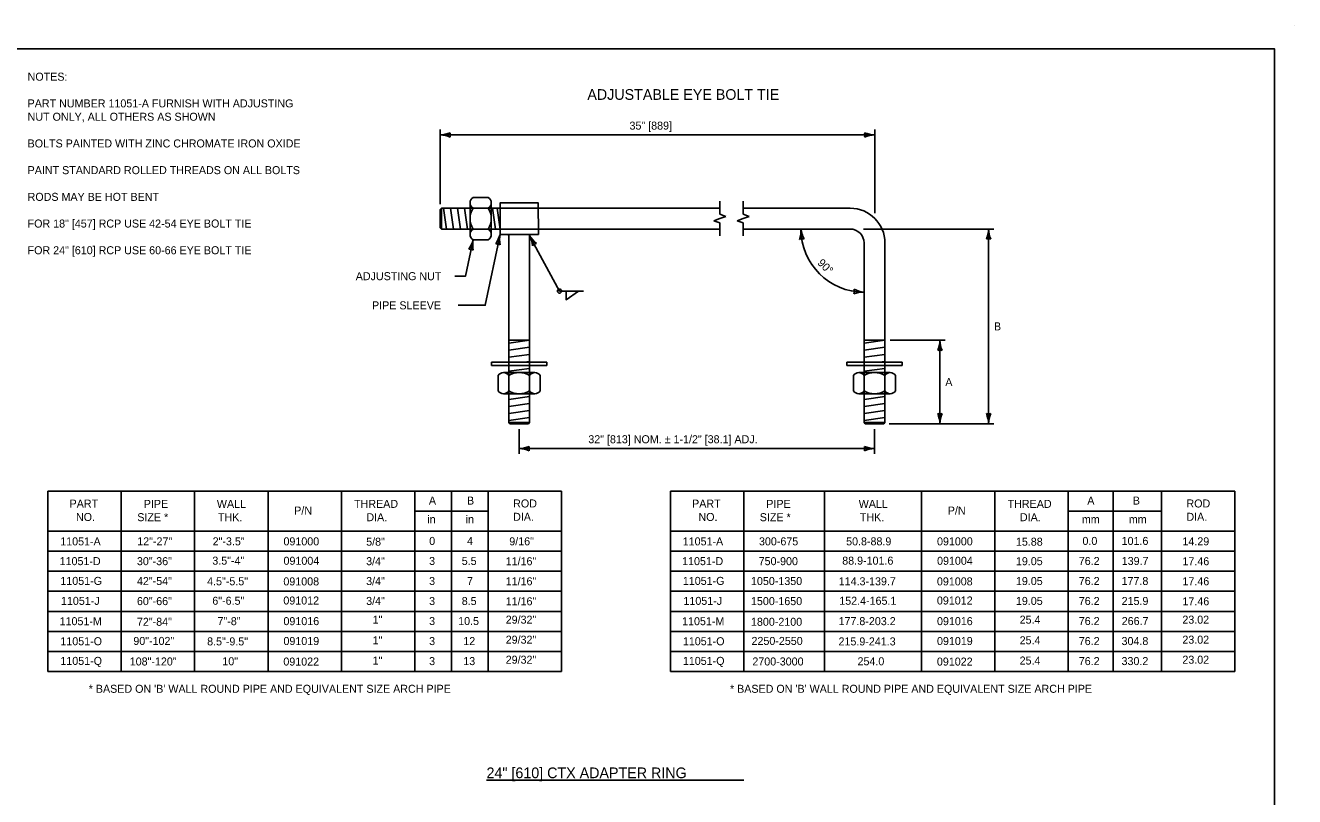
# Model space of a CAD drawing. Extents: x 49991.4 to 50021, y 49987.6 to 50011.4.
# Drawn here: x 50007.38 to 50016.9, y 49993.4 to 49999.18 of the extents above; entities that cross this region are included whole.
import ezdxf

# ---------------------------------------------------------------- set-up
doc = ezdxf.new("R2010")
doc.units = 0
for name, color, linetype in [('Level 1', 7, 'Continuous'), ('Level 2', 7, 'Continuous'), ('Level 3', 7, 'Continuous'), ('Level 4', 7, 'Continuous'), ('Level 6', 7, 'Continuous')]:
    doc.layers.add(name, color=color, linetype=linetype)

# ---------------------------------------------------------------- blocks, each defined once
blk = doc.blocks.new('HCUT')
at = {"layer": 'Level 6'}
for p, q in [((-0.0324, 0.0914), (-0.0648, 0)), ((-0.0324, 0.0914), (0, 0)), ((0, 0), (0.0324, -0.0914)), ((0.0648, 0), (0.0324, -0.0914))]:
    blk.add_line(p, q, dxfattribs=at)

msp = doc.modelspace()

# ---------------------------------------------------------------- linework, layer by layer
at = {"layer": 'Level 1'}
for p, q in [((50016.9001, 49999.1756), (50016.9001, 49999.1756)), ((50010.855, 49997.8864), (50010.7412, 49997.8864)), ((50010.4943, 49997.7976), (50010.5033, 49997.8066)), ((50010.4943, 49997.6593), (50010.4943, 49997.7976)), ((50010.5033, 49997.8066), (50010.9431, 49997.8066)), ((50010.5033, 49997.6504), (50010.5033, 49997.8066)), ((50010.5408, 49997.6504), (50010.5189, 49997.8066)), ((50010.5934, 49997.6504), (50010.5715, 49997.8066)), ((50010.646, 49997.6504), (50010.6241, 49997.8066)), ((50010.6986, 49997.6504), (50010.6766, 49997.8066)), ((50010.7188, 49997.6103), (50010.7188, 49997.8466)), ((50010.8774, 49997.6103), (50010.8774, 49997.8466)), ((50010.9089, 49997.6504), (50010.887, 49997.8066)), ((50010.9431, 49997.6504), (50010.9212, 49997.8066)), ((50011.2304, 49997.8066), (50012.5911, 49997.8066)), ((50012.7659, 49997.8066), (50013.5682, 49997.8066)), ((50010.4943, 49997.6593), (50010.5033, 49997.6504)), ((50010.5033, 49997.6504), (50010.9431, 49997.6504)), ((50011.0086, 49997.6104), (50011.0086, 49996.201)), ((50011.0086, 49997.6011), (50011.0086, 49997.6104)), ((50011.0086, 49997.6104), (50011.0086, 49997.6004)), ((50011.1649, 49997.6104), (50011.1649, 49996.201)), ((50011.1649, 49997.6011), (50011.1649, 49997.6104)), ((50011.1649, 49997.6104), (50011.1649, 49997.6094)), ((50011.1649, 49997.6104), (50011.1649, 49997.6004)), ((50011.2304, 49997.6504), (50012.5911, 49997.6504)), ((50012.7659, 49997.6504), (50013.5682, 49997.6504)), ((50010.855, 49997.5706), (50010.7412, 49997.5706)), ((50013.6723, 49997.5462), (50013.6723, 49996.201)), ((50013.8286, 49997.5462), (50013.8286, 49996.201)), ((50011.1649, 49996.817), (50011.0086, 49996.7951)), ((50011.1649, 49996.817), (50011.0086, 49996.817)), ((50011.1649, 49996.7644), (50011.0086, 49996.7425)), ((50013.8286, 49996.817), (50013.6723, 49996.7951)), ((50013.8286, 49996.817), (50013.6723, 49996.817)), ((50013.8286, 49996.7644), (50013.6723, 49996.7425)), ((50011.2951, 49996.6532), (50010.8784, 49996.6532)), ((50010.8784, 49996.6272), (50010.8784, 49996.6532)), ((50011.1649, 49996.7118), (50011.0086, 49996.6899)), ((50011.1649, 49996.6592), (50011.1221, 49996.6532)), ((50011.2951, 49996.6272), (50011.2951, 49996.6532)), ((50013.5421, 49996.6272), (50013.5421, 49996.6532)), ((50013.9588, 49996.6532), (50013.5421, 49996.6532)), ((50013.8286, 49996.7118), (50013.6723, 49996.6899)), ((50013.8286, 49996.6592), (50013.7858, 49996.6532)), ((50013.9588, 49996.6272), (50013.9588, 49996.6532)), ((50011.2951, 49996.6272), (50010.8784, 49996.6272)), ((50010.9289, 49996.5527), (50010.9289, 49996.439)), ((50011.2049, 49996.5751), (50010.9686, 49996.5751)), ((50011.1649, 49996.6067), (50011.0086, 49996.5847)), ((50011.2446, 49996.5527), (50011.2446, 49996.439)), ((50013.9588, 49996.6272), (50013.5421, 49996.6272)), ((50013.5926, 49996.5527), (50013.5926, 49996.439)), ((50013.8686, 49996.5751), (50013.6323, 49996.5751)), ((50013.8286, 49996.6067), (50013.6723, 49996.5847)), ((50013.9083, 49996.5527), (50013.9083, 49996.439)), ((50011.2049, 49996.4166), (50010.9686, 49996.4166)), ((50011.1649, 49996.3963), (50011.0086, 49996.3744)), ((50013.8686, 49996.4166), (50013.6323, 49996.4166)), ((50013.8286, 49996.3963), (50013.6723, 49996.3744)), ((50011.1649, 49996.3437), (50011.0086, 49996.3218)), ((50011.1649, 49996.2911), (50011.0086, 49996.2692)), ((50013.8286, 49996.3437), (50013.6723, 49996.3218)), ((50013.8286, 49996.2911), (50013.6723, 49996.2692)), ((50011.1649, 49996.2385), (50011.0086, 49996.2166)), ((50011.1649, 49996.201), (50011.0086, 49996.201)), ((50011.0176, 49996.192), (50011.0086, 49996.201)), ((50011.1559, 49996.192), (50011.0176, 49996.192)), ((50011.1559, 49996.192), (50011.1649, 49996.201)), ((50013.8286, 49996.2385), (50013.6723, 49996.2166)), ((50013.8286, 49996.201), (50013.6723, 49996.201)), ((50013.6813, 49996.192), (50013.6723, 49996.201)), ((50013.8196, 49996.192), (50013.6813, 49996.192)), ((50013.8196, 49996.192), (50013.8286, 49996.201))]:
    msp.add_line(p, q, dxfattribs=at)
for points in [[(49999.3835, 49998.9992), (50016.7501, 49998.9992), (50016.7501, 49987.7988), (49999.3835, 49987.7988)], [(50011.2304, 49997.6104), (50010.9431, 49997.6104), (50010.9431, 49997.8466), (50011.2303, 49997.8466)]]:
    msp.add_lwpolyline(points, close=True, dxfattribs=at)
for centre, radius, start, end in [((50010.7653, 49997.8466), 0.0465, 121.20341, 238.79659), ((50010.8309, 49997.8466), 0.0465, 301.20341, 58.79659), ((50010.8672, 49997.7285), 0.1484, 148.10921, 211.89079), ((50010.729, 49997.7285), 0.1484, 328.10921, 31.89079), ((50013.5682, 49997.5462), 0.2604, 0, 90), ((50010.7653, 49997.6103), 0.0465, 121.20341, 238.79659), ((50010.8309, 49997.6103), 0.0465, 301.20341, 58.79659), ((50010.9986, 49997.6004), 0.01, 0, 90), ((50011.1749, 49997.6004), 0.01, 90, 180), ((50013.5682, 49997.5462), 0.1042, 0, 90), ((50010.9686, 49996.5287), 0.0465, 31.20341, 148.79659), ((50011.0867, 49996.4268), 0.1484, 58.10921, 121.89079), ((50011.2049, 49996.5287), 0.0465, 31.20341, 148.79659), ((50013.6323, 49996.5287), 0.0465, 31.20341, 148.79659), ((50013.7505, 49996.4268), 0.1484, 58.10921, 121.89079), ((50013.8686, 49996.5287), 0.0465, 31.20341, 148.79659), ((50010.9686, 49996.463), 0.0465, 211.20341, 328.79659), ((50011.0867, 49996.5649), 0.1484, 238.10921, 301.89079), ((50011.2049, 49996.463), 0.0465, 211.20341, 328.79659), ((50013.6323, 49996.463), 0.0465, 211.20341, 328.79659), ((50013.7505, 49996.5649), 0.1484, 238.10921, 301.89079), ((50013.8686, 49996.463), 0.0465, 211.20341, 328.79659)]:
    msp.add_arc(centre, radius, start, end, dxfattribs=at)
at = {"layer": 'Level 2'}
for p, q in [((50007.5537, 49995.6868), (50011.4037, 49995.6868)), ((50007.5537, 49995.6868), (50007.5537, 49994.3368)), ((50007.5537, 49995.6868), (50007.8287, 49995.6868)), ((50008.1037, 49995.6868), (50008.1037, 49994.3368)), ((50008.6537, 49995.6868), (50008.6537, 49994.3368)), ((50009.2037, 49995.6868), (50009.2037, 49994.3368)), ((50009.7537, 49995.6868), (50009.7537, 49994.3368)), ((50010.3037, 49995.6868), (50010.3037, 49994.3368)), ((50010.5787, 49995.6868), (50010.5787, 49994.3368)), ((50010.8537, 49995.6868), (50010.8537, 49994.3368)), ((50011.4037, 49995.6868), (50011.4037, 49994.3368)), ((50012.2204, 49995.6868), (50012.2204, 49994.3368)), ((50012.2204, 49995.6868), (50012.4954, 49995.6868)), ((50012.3611, 49995.6868), (50016.4514, 49995.6868)), ((50012.7704, 49995.6868), (50012.7704, 49994.3368)), ((50013.3769, 49995.6868), (50013.3769, 49994.3368)), ((50014.1033, 49995.6868), (50014.1033, 49994.3368)), ((50014.6533, 49995.6868), (50014.6533, 49994.3368)), ((50015.2033, 49995.6868), (50015.2033, 49994.3368)), ((50015.541, 49995.6868), (50015.541, 49994.3368)), ((50015.9014, 49995.6868), (50015.9014, 49994.3368)), ((50016.4514, 49995.6868), (50016.4514, 49994.3368)), ((50007.5537, 49995.3868), (50011.4037, 49995.3868)), ((50012.2204, 49995.3868), (50016.4514, 49995.3868)), ((50007.5537, 49995.2368), (50011.4037, 49995.2368)), ((50012.2204, 49995.2368), (50016.4514, 49995.2368)), ((50007.5537, 49995.0868), (50011.4037, 49995.0868)), ((50012.2204, 49995.0868), (50016.4514, 49995.0868)), ((50007.5537, 49994.9368), (50011.4037, 49994.9368)), ((50012.2204, 49994.9368), (50016.4514, 49994.9368)), ((50007.5537, 49994.7868), (50011.4037, 49994.7868)), ((50012.2204, 49994.7868), (50016.4514, 49994.7868)), ((50007.5537, 49994.6368), (50011.4037, 49994.6368)), ((50012.2204, 49994.6368), (50016.4514, 49994.6368)), ((50007.5537, 49994.4868), (50011.4037, 49994.4868)), ((50012.2204, 49994.4868), (50016.4514, 49994.4868)), ((50007.5537, 49994.3368), (50011.4037, 49994.3368)), ((50012.2204, 49994.3368), (50016.4514, 49994.3368)), ((50010.842, 49993.5213), (50012.7707, 49993.5213))]:
    msp.add_line(p, q, dxfattribs=at)
for points in [[(50010.3037, 49995.5368), (50010.3037, 49995.5368), (50010.3037, 49995.5368), (50010.8537, 49995.5368)], [(50015.2033, 49995.5368), (50015.9014, 49995.5368)]]:
    msp.add_lwpolyline(points, dxfattribs=at)
at = {"layer": 'Level 3'}
for p, q in [((50010.4943, 49997.8376), (50010.4943, 49998.395)), ((50013.7523, 49997.7703), (50013.7523, 49998.395)), ((50010.4943, 49998.355), (50013.7523, 49998.355)), ((50013.2863, 49997.6504), (50013.1593, 49997.6504)), ((50013.6682, 49997.6504), (50014.6461, 49997.6504)), ((50014.6061, 49997.6504), (50014.6061, 49996.192)), ((50013.6723, 49997.2458), (50013.6723, 49997.1374)), ((50013.8686, 49996.817), (50014.2812, 49996.817)), ((50014.2412, 49996.192), (50014.2412, 49996.817)), ((50013.8596, 49996.192), (50014.6461, 49996.192)), ((50013.8596, 49996.192), (50014.2812, 49996.192)), ((50011.0867, 49996.152), (50011.0867, 49995.9659)), ((50013.7505, 49996.152), (50013.7505, 49995.9659)), ((50011.0867, 49996.0059), (50013.7505, 49996.0059))]:
    msp.add_line(p, q, dxfattribs=at)
for points in [[(50010.9431, 49997.6104), (50010.832, 49997.079), (50010.6284, 49997.079)], [(50011.1649, 49997.6004), (50011.3891, 49997.1853), (50011.5693, 49997.1853)], [(50010.7412, 49997.5706), (50010.6836, 49997.2972), (50010.6052, 49997.2972)], [(50011.4382, 49997.1853), (50011.4382, 49997.1206), (50011.531, 49997.1853)]]:
    msp.add_lwpolyline(points, dxfattribs=at)
msp.add_circle((50011.3891, 49997.1853), 0.0156, dxfattribs=at)
for centre, radius, start, end in [((50010.4829, 49998.5877), 0.233, 272.81025, 292.0601), ((50010.6225, 49998.3549), 0.0548, 162.12175, 197.84411), ((50013.7615, 49998.5771), 0.2223, 247.43895, 267.62245), ((50013.6241, 49998.355), 0.0548, 342.12175, 17.84411), ((50010.4851, 49998.1329), 0.2223, 67.43895, 87.62245), ((50013.7637, 49998.1223), 0.233, 92.81025, 112.0601), ((50010.7276, 49997.6649), 0.2223, 325.62049, 345.80399), ((50011.1733, 49997.5739), 0.233, 170.99179, 190.24164), ((50010.9651, 49997.5028), 0.2223, 5.83512, 26.01862), ((50011.3642, 49997.7211), 0.233, 211.20642, 230.45627), ((50012.9772, 49997.642), 0.2223, 341.96334, 2.14685), ((50013.6723, 49997.6504), 0.473, 180, 270), ((50013.4304, 49997.6801), 0.233, 187.33464, 206.58449), ((50014.384, 49997.6596), 0.2223, 337.43895, 357.62245), ((50014.8389, 49997.6618), 0.233, 182.81025, 202.0601), ((50010.5258, 49997.6254), 0.2223, 325.53304, 345.71655), ((50010.9713, 49997.5338), 0.233, 170.90434, 190.15419), ((50010.9168, 49997.4849), 0.0548, 60.30329, 96.02566), ((50011.2258, 49997.4875), 0.0548, 100.51792, 136.24028), ((50013.2094, 49997.5225), 0.0548, 76.64615, 112.36851), ((50014.6061, 49997.5221), 0.0548, 72.12175, 107.84411), ((50010.7147, 49997.4451), 0.0548, 60.21585, 95.93821), ((50013.5444, 49997.1864), 0.0548, 338.11546, 13.83782), ((50013.6675, 49996.9444), 0.233, 88.80395, 108.0538), ((50013.697, 49997.3983), 0.2223, 243.43265, 263.61616), ((50014.0191, 49996.8262), 0.2223, 337.43895, 357.62245), ((50014.2412, 49996.6888), 0.0548, 72.12175, 107.84411), ((50014.4739, 49996.8284), 0.233, 182.81025, 202.0601), ((50014.2413, 49996.3202), 0.0548, 252.12175, 287.84411), ((50014.0085, 49996.1806), 0.233, 2.81025, 22.0601), ((50014.4634, 49996.1828), 0.2223, 157.43895, 177.62245), ((50014.6062, 49996.3202), 0.0548, 252.12175, 287.84411), ((50014.3734, 49996.1806), 0.233, 2.81025, 22.0601), ((50014.8283, 49996.1828), 0.2223, 157.43895, 177.62245), ((50011.0753, 49996.2386), 0.233, 272.81025, 292.0601), ((50011.0775, 49995.7838), 0.2223, 67.43895, 87.62245), ((50011.215, 49996.0059), 0.0548, 162.12175, 197.84411), ((50013.7597, 49996.228), 0.2223, 247.43895, 267.62245), ((50013.6222, 49996.006), 0.0548, 342.12175, 17.84411), ((50013.7619, 49995.7732), 0.233, 92.81025, 112.0601)]:
    msp.add_arc(centre, radius, start, end, dxfattribs=at)
at = {"layer": 'Level 4'}
for p, q in [((50010.9431, 49997.8066), (50011.2304, 49997.8066)), ((50011.2304, 49997.6504), (50010.9431, 49997.6504))]:
    msp.add_line(p, q, dxfattribs=at)
at = {"layer": 'Level 6'}
for p, q in [((50012.5911, 49997.7609), (50012.5911, 49997.8587)), ((50012.7659, 49997.7609), (50012.7659, 49997.8587)), ((50012.5911, 49997.6961), (50012.5911, 49997.5983)), ((50012.7659, 49997.6961), (50012.7659, 49997.5983))]:
    msp.add_line(p, q, dxfattribs=at)

# ---------------------------------------------------------------- block references
at = {"layer": 'Level 6', "xscale": 0.5, "yscale": 0.5, "rotation": 90}
for p in [(50012.5911, 49997.7285), (50012.7659, 49997.7285)]:
    msp.add_blockref('HCUT', p, dxfattribs=at)

# ---------------------------------------------------------------- texts
at = {"layer": 'Level 2'}
for s, height, p in [('NOTES:', 0.06, (50007.4015, 49998.7615)), ('ADJUSTABLE EYE BOLT TIE', 0.08, (50011.5978, 49998.6181)), ('PART NUMBER 11051-A FURNISH WITH ADJUSTING', 0.06, (50007.4015, 49998.5615)), ('NUT ONLY, ALL OTHERS AS SHOWN', 0.06, (50007.4015, 49998.4615)), ('35" [889]', 0.06, (50011.9139, 49998.395)), ('BOLTS PAINTED WITH ZINC CHROMATE IRON OXIDE ', 0.06, (50007.4015, 49998.2615)), ('PAINT STANDARD ROLLED THREADS ON ALL BOLTS', 0.06, (50007.4015, 49998.0615)), ('RODS MAY BE HOT BENT', 0.06, (50007.4015, 49997.8615)), ('FOR 18" [457] RCP USE 42-54 EYE BOLT TIE', 0.06, (50007.4015, 49997.6615)), ('FOR 24" [610] RCP USE 60-66 EYE BOLT TIE', 0.06, (50007.4015, 49997.4615)), ('ADJUSTING NUT', 0.06, (50009.8613, 49997.2672)), ('PIPE SLEEVE', 0.06, (50009.9836, 49997.049)), ('32" [813] NOM. ± 1-1/2" [38.1] ADJ.', 0.06, (50011.6049, 49996.0459)), ('PART', 0.06, (50007.7163, 49995.5638)), ('PIPE', 0.06, (50008.2724, 49995.5621)), ('WALL', 0.06, (50008.8204, 49995.5621)), ('THREAD', 0.06, (50009.8489, 49995.5621)), ('A', 0.06, (50010.4099, 49995.5865)), ('B', 0.06, (50010.6955, 49995.5865)), ('ROD', 0.06, (50011.0415, 49995.5649)), ('PART', 0.06, (50012.383, 49995.5638)), ('PIPE', 0.06, (50012.9392, 49995.5621)), ('WALL', 0.06, (50013.6321, 49995.5621)), ('THREAD', 0.06, (50014.7485, 49995.5621)), ('A', 0.06, (50015.3459, 49995.5865)), ('B', 0.06, (50015.6871, 49995.5865)), ('ROD', 0.06, (50016.0892, 49995.5649)), ('NO.', 0.06, (50007.7641, 49995.4638)), ('SIZE *', 0.06, (50008.2237, 49995.4621)), ('THK.', 0.06, (50008.8286, 49995.4621)), ('P/N', 0.06, (50009.4003, 49995.5121)), ('DIA.', 0.06, (50009.9413, 49995.4621)), ('in', 0.06, (50010.3983, 49995.4463)), ('in', 0.06, (50010.6859, 49995.4463)), ('DIA.', 0.06, (50011.0413, 49995.4649)), ('NO.', 0.06, (50012.4308, 49995.4638)), ('SIZE *', 0.06, (50012.8904, 49995.4621)), ('THK.', 0.06, (50013.6403, 49995.4621)), ('P/N', 0.06, (50014.2999, 49995.5121)), ('DIA.', 0.06, (50014.8409, 49995.4621)), ('DIA.', 0.06, (50016.089, 49995.4649)), ('mm', 0.06, (50015.3051, 49995.4463)), ('mm', 0.06, (50015.6572, 49995.4463)), ('11051-A', 0.06, (50007.6461, 49995.2809)), ('12"-27"', 0.06, (50008.2234, 49995.2811)), ('2"-3.5"', 0.06, (50008.7886, 49995.2811)), ('091000', 0.06, (50009.3197, 49995.2811)), ('5/8"', 0.06, (50009.9396, 49995.2785)), ('0', 0.06, (50010.4123, 49995.2843)), ('4', 0.06, (50010.6959, 49995.2843)), ('9/16"', 0.06, (50011.0126, 49995.2814)), ('11051-A', 0.06, (50012.3128, 49995.2809)), ('300-675', 0.06, (50012.8845, 49995.2811)), ('50.8-88.9', 0.06, (50013.5378, 49995.2811)), ('091000', 0.06, (50014.2193, 49995.2811)), ('15.88', 0.06, (50014.8107, 49995.2785)), ('0.0', 0.06, (50015.3096, 49995.2843)), ('101.6', 0.06, (50015.6031, 49995.2843)), ('14.29', 0.06, (50016.0592, 49995.2814)), ('11051-D', 0.06, (50007.6415, 49995.1329)), ('30"-36"', 0.06, (50008.2211, 49995.1327)), ('3.5"-4"', 0.06, (50008.7862, 49995.1366)), ('091004', 0.06, (50009.32, 49995.1357)), ('3/4"', 0.06, (50009.9396, 49995.1326)), ('3', 0.06, (50010.4115, 49995.1343)), ('5.5', 0.06, (50010.6562, 49995.1343)), ('11/16"', 0.06, (50010.9857, 49995.1321)), ('11051-D', 0.06, (50012.3082, 49995.1329)), ('750-900', 0.06, (50012.8821, 49995.1327)), ('88.9-101.6', 0.06, (50013.5085, 49995.1366)), ('091004', 0.06, (50014.2196, 49995.1357)), ('19.05', 0.06, (50014.8107, 49995.1326)), ('76.2', 0.06, (50015.2819, 49995.1343)), ('139.7', 0.06, (50015.6039, 49995.1343)), ('17.46', 0.06, (50016.0592, 49995.1321)), ('11051-G', 0.06, (50007.647, 49994.9849)), ('42"-54"', 0.06, (50008.2211, 49994.9839)), ('4.5"-5.5"', 0.06, (50008.7474, 49994.9821)), ('091008', 0.06, (50009.319, 49994.9812)), ('3/4"', 0.06, (50009.9396, 49994.9838)), ('3', 0.06, (50010.4115, 49994.9843)), ('7', 0.06, (50010.6961, 49994.9843)), ('11/16"', 0.06, (50010.9857, 49994.9821)), ('11051-G', 0.06, (50012.3137, 49994.9849)), ('1050-1350', 0.06, (50012.8246, 49994.9839)), ('114.3-139.7', 0.06, (50013.4822, 49994.9821)), ('091008', 0.06, (50014.2186, 49994.9812)), ('19.05', 0.06, (50014.8107, 49994.9838)), ('76.2', 0.06, (50015.2819, 49994.9843)), ('177.8', 0.06, (50015.6027, 49994.9843)), ('17.46', 0.06, (50016.0592, 49994.9821)), ('11051-J', 0.06, (50007.6515, 49994.8354)), ('60"-66"', 0.06, (50008.2211, 49994.8335)), ('6"-6.5"', 0.06, (50008.7862, 49994.8362)), ('091012', 0.06, (50009.3188, 49994.8381)), ('3/4"', 0.06, (50009.9396, 49994.8349)), ('3', 0.06, (50010.4115, 49994.8343)), ('8.5', 0.06, (50010.6562, 49994.8343)), ('11/16"', 0.06, (50010.9857, 49994.8321)), ('11051-J', 0.06, (50012.3182, 49994.8354)), ('1500-1650', 0.06, (50012.8246, 49994.8335)), ('152.4-165.1', 0.06, (50013.4863, 49994.8362)), ('091012', 0.06, (50014.2184, 49994.8381)), ('19.05', 0.06, (50014.8107, 49994.8349)), ('76.2', 0.06, (50015.2819, 49994.8343)), ('215.9', 0.06, (50015.6031, 49994.8343)), ('17.46', 0.06, (50016.0592, 49994.8321)), ('11051-M', 0.06, (50007.6413, 49994.6831)), ('7"-8"', 0.06, (50008.825, 49994.6834)), ('091016', 0.06, (50009.3195, 49994.6835)), ('1"', 0.06, (50009.9883, 49994.6947)), ('3', 0.06, (50010.4115, 49994.6843)), ('10.5', 0.06, (50010.6293, 49994.6843)), ('29/32"', 0.06, (50010.9857, 49994.6947)), ('11051-M', 0.06, (50012.3081, 49994.6831)), ('177.8-203.2', 0.06, (50013.4809, 49994.6834)), ('091016', 0.06, (50014.2191, 49994.6835)), ('25.4', 0.06, (50014.8386, 49994.6947)), ('76.2', 0.06, (50015.2819, 49994.6843)), ('266.7', 0.06, (50015.6039, 49994.6843)), ('23.02', 0.06, (50016.0586, 49994.6947)), ('72"-84"', 0.06, (50008.2211, 49994.6787)), ('1800-2100', 0.06, (50012.8246, 49994.6787)), ('11051-O', 0.06, (50007.6471, 49994.5329)), ('90"-102"', 0.06, (50008.1941, 49994.5352)), ('8.5"-9.5"', 0.06, (50008.7474, 49994.5317)), ('091019', 0.06, (50009.3195, 49994.5345)), ('1"', 0.06, (50009.9883, 49994.5402)), ('3', 0.06, (50010.4115, 49994.5343)), ('12', 0.06, (50010.6678, 49994.5343)), ('29/32"', 0.06, (50010.9857, 49994.5447)), ('11051-O', 0.06, (50012.3139, 49994.5329)), ('2250-2550', 0.06, (50012.8285, 49994.5352)), ('215.9-241.3', 0.06, (50013.4808, 49994.5317)), ('091019', 0.06, (50014.2191, 49994.5345)), ('25.4', 0.06, (50014.8386, 49994.5402)), ('76.2', 0.06, (50015.2819, 49994.5343)), ('304.8', 0.06, (50015.6027, 49994.5343)), ('23.02', 0.06, (50016.0586, 49994.5447)), ('29/32"', 0.06, (50010.9857, 49994.3947)), ('11051-Q', 0.06, (50007.6471, 49994.3857)), ('108"-120"', 0.06, (50008.1672, 49994.3815)), ('10"', 0.06, (50008.8614, 49994.3829)), ('091022', 0.06, (50009.3188, 49994.3807)), ('1"', 0.06, (50009.9883, 49994.3885)), ('3', 0.06, (50010.4115, 49994.3843)), ('13', 0.06, (50010.6677, 49994.3843)), ('11051-Q', 0.06, (50012.3139, 49994.3857)), ('2700-3000', 0.06, (50012.835, 49994.3815)), ('254.0', 0.06, (50013.6233, 49994.3829)), ('091022', 0.06, (50014.2184, 49994.3807)), ('25.4', 0.06, (50014.8386, 49994.3885)), ('76.2', 0.06, (50015.2819, 49994.3843)), ('330.2', 0.06, (50015.6025, 49994.3843)), ('23.02', 0.06, (50016.0586, 49994.3947)), ("* BASED ON 'B' WALL ROUND PIPE AND EQUIVALENT SIZE ARCH PIPE", 0.06, (50007.8597, 49994.1768)), ("* BASED ON 'B' WALL ROUND PIPE AND EQUIVALENT SIZE ARCH PIPE", 0.06, (50012.6671, 49994.1768))]:
    msp.add_text(s, height=height, dxfattribs=at).set_placement(p)
for s, height, rotation, p in [('90°', 0.06, 315, (50013.3187, 49997.3917)), ('B', 0.06, 360, (50014.6461, 49996.8912)), ('A', 0.06, 360, (50014.2812, 49996.4745)), ('24" [610] CTX ADAPTER RING', 0.08, 360, (50010.842, 49993.5373))]:
    msp.add_text(s, height=height, rotation=rotation, dxfattribs=at).set_placement(p)

doc.saveas('drawing.dxf')
